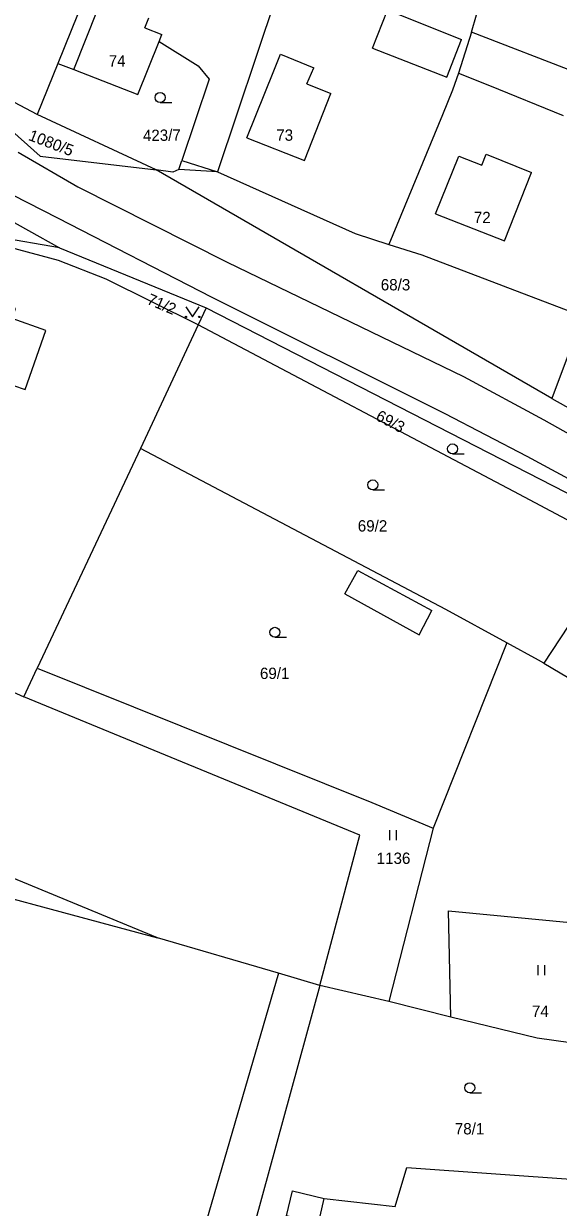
# Model space of a CAD drawing. Extents: x -746176 to -739709, y -1127410 to -1124482.
# Drawn here: x -742472.1 to -742391.9, y -1126088.1 to -1125910.5 of the extents above; entities that cross this region are included whole.
import ezdxf

# ---------------------------------------------------------------- set-up
doc = ezdxf.new("R2010")
doc.units = 0
for name, color, linetype in [('Hranice parcel', 7, 'Continuous'), ('Parcelní čísla', 7, 'Continuous'), ('Vnitřní kresba', 7, 'Continuous'), ('Značky kultur', 7, 'Continuous')]:
    doc.layers.add(name, color=color, linetype=linetype)

msp = doc.modelspace()

# ---------------------------------------------------------------- linework, layer by layer
at = {"layer": 'Hranice parcel'}
for p, q in [((-742459.32, -1125897.41), (-742466.99, -1125916.45)), ((-742404.91, -1125911.78), (-742401.44, -1125899.49)), ((-742433.58, -1125904.47), (-742443.02, -1125932.7)), ((-742470.08, -1125924.13), (-742486.25, -1125915.58)), ((-742466.99, -1125916.45), (-742470.08, -1125924.13)), ((-742452.23, -1125932.44), (-742470.08, -1125924.13)), ((-742392.86, -1125966.72), (-742452.23, -1125932.44)), ((-742485.76, -1125933.54), (-742466.73, -1125944.13)), ((-742466.73, -1125944.13), (-742444.75, -1125953.11)), ((-742444.75, -1125953.11), (-742445.94, -1125955.65)), ((-742445.94, -1125955.65), (-742454.6, -1125974.2)), ((-742454.6, -1125974.2), (-742470.09, -1126007.17)), ((-742399.65, -1126003.37), (-742410.68, -1126031.18)), ((-742472.11, -1126011.47), (-742470.09, -1126007.17)), ((-742452.02, -1126047.65), (-742529.61, -1126015.62)), ((-742410.68, -1126031.18), (-742417.35, -1126057.17)), ((-742433.87, -1126052.94), (-742452.02, -1126047.65)), ((-742427.68, -1126054.77), (-742433.87, -1126052.94)), ((-742417.35, -1126057.17), (-742427.68, -1126054.77)), ((-742408.01, -1126059.51), (-742417.35, -1126057.17))]:
    msp.add_line(p, q, dxfattribs=at)
for points in [[(-742466.99, -1125916.45), (-742464.6, -1125917.38), (-742455, -1125921.11), (-742451.78, -1125913.15), (-742445.93, -1125916.84), (-742444.31, -1125918.83), (-742448.37, -1125931), (-742443.02, -1125932.7)], [(-742404.91, -1125911.78), (-742406.86, -1125917.94), (-742407.78, -1125920.45), (-742409.26, -1125924.16), (-742417.31, -1125943.6)], [(-742376.04, -1125923.32), (-742388.87, -1125917.99), (-742404.91, -1125911.78)], [(-742486.25, -1125915.58), (-742469.64, -1125930.37), (-742452.23, -1125932.44)], [(-742443.02, -1125932.7), (-742448.82, -1125932.36), (-742449.74, -1125932.78), (-742452.23, -1125932.44)], [(-742443.02, -1125932.7), (-742422.4, -1125941.96), (-742417.31, -1125943.6)], [(-742466.73, -1125944.13), (-742476.04, -1125942.52), (-742485.91, -1125941.93), (-742509.68, -1125946.54)], [(-742445.94, -1125955.65), (-742459.75, -1125948.8), (-742466.89, -1125946.02), (-742474.13, -1125944.08), (-742476.37, -1125943.84), (-742485.83, -1125943.85), (-742509.68, -1125946.54)], [(-742417.31, -1125943.6), (-742412.38, -1125945.19), (-742387.99, -1125954.45)], [(-742480.68, -1125962.42), (-742481.12, -1125963.73), (-742480.27, -1125964.02), (-742480.78, -1125965.52), (-742479, -1125966.12), (-742478.49, -1125964.62), (-742477.64, -1125964.9), (-742477.2, -1125963.59), (-742471.89, -1125965.38), (-742468.82, -1125956.52), (-742473.86, -1125954.74), (-742473.34, -1125953.24), (-742475.63, -1125952.43), (-742475.36, -1125951.69), (-742476.67, -1125951.22), (-742476.32, -1125950.24), (-742478.09, -1125949.62), (-742478.44, -1125950.6), (-742479.71, -1125950.15), (-742479.97, -1125950.9), (-742482.31, -1125950.08), (-742485.99, -1125960.63), (-742480.68, -1125962.42)], [(-742444.75, -1125953.11), (-742386.93, -1125982.77), (-742380.97, -1125986.53)], [(-742382.69, -1125989.14), (-742398.6, -1125980.67), (-742445.94, -1125955.65)], [(-742387.99, -1125954.45), (-742389.36, -1125957.36), (-742392.86, -1125966.72)], [(-742392.86, -1125966.72), (-742375.94, -1125976.23), (-742374.7, -1125977.14), (-742365.43, -1125982.55)], [(-742399.65, -1126003.37), (-742408.8, -1125998.36), (-742454.6, -1125974.2)], [(-742525.42, -1125987.39), (-742524.92, -1125987.63), (-742472.11, -1126011.47)], [(-742382.69, -1125989.14), (-742385.4, -1125993.25), (-742394.08, -1126006.45)], [(-742394.08, -1126006.45), (-742394.87, -1126005.98), (-742399.65, -1126003.37)], [(-742470.09, -1126007.17), (-742419.86, -1126027.33), (-742410.68, -1126031.18)], [(-742394.08, -1126006.45), (-742377.42, -1126016.26), (-742373.55, -1126018.6), (-742347.83, -1126023.87), (-742347.76, -1126023.57)], [(-742427.68, -1126054.77), (-742421.67, -1126032.23), (-742472.11, -1126011.47)], [(-742530.79, -1126023.12), (-742529.6, -1126023.26), (-742518.21, -1126026.98), (-742517.74, -1126027.24), (-742518.78, -1126030.97), (-742491.05, -1126037.15), (-742452.02, -1126047.65)], [(-742408.01, -1126059.51), (-742408.36, -1126043.59), (-742380.73, -1126046.24)], [(-742433.87, -1126052.94), (-742447.8, -1126100.68), (-742456.41, -1126109.29), (-742463.16, -1126192.21), (-742472.54, -1126297.27), (-742476.24, -1126360.79), (-742482.39, -1126414.71)], [(-742427.68, -1126054.77), (-742440.74, -1126102.42), (-742430.76, -1126104.41), (-742424.03, -1126105.75), (-742421.29, -1126105.88)], [(-742374.74, -1126065.53), (-742395.07, -1126062.68), (-742408.01, -1126059.51)], [(-742421.29, -1126105.88), (-742421.35, -1126098.94), (-742420.61, -1126091.6), (-742427.91, -1126090.46), (-742432.7, -1126089.32), (-742431.8, -1126085.57), (-742427.02, -1126086.71), (-742416.37, -1126087.94), (-742414.61, -1126082.07), (-742388.6, -1126083.94), (-742388.43, -1126090.91), (-742379.6, -1126093.36)]]:
    msp.add_lwpolyline(points, dxfattribs=at)
at = {"layer": 'Vnitřní kresba'}
for p, q in [((-742464.6, -1125917.38), (-742461.01, -1125908.34)), ((-742453.97, -1125911.14), (-742453.33, -1125909.63)), ((-742419.77, -1125914.17), (-742417.54, -1125908.45)), ((-742416.34, -1125908.93), (-742406.43, -1125912.88)), ((-742453.97, -1125911.14), (-742451.37, -1125912.13)), ((-742451.78, -1125913.15), (-742451.37, -1125912.13)), ((-742408.63, -1125918.53), (-742406.43, -1125912.88)), ((-742419.77, -1125914.17), (-742408.63, -1125918.53)), ((-742434.59, -1125917.55), (-742433.61, -1125915.09)), ((-742433.61, -1125915.09), (-742428.57, -1125917.11)), ((-742438.62, -1125927.64), (-742434.59, -1125917.55)), ((-742429.64, -1125919.52), (-742428.57, -1125917.11)), ((-742406.86, -1125917.94), (-742402.22, -1125919.77)), ((-742429.64, -1125919.52), (-742426.02, -1125920.95)), ((-742402.22, -1125919.77), (-742391.15, -1125924.26)), ((-742430.01, -1125931), (-742426.02, -1125920.95)), ((-742438.62, -1125927.64), (-742430.01, -1125931)), ((-742472.93, -1125929.77), (-742464.02, -1125934.96)), ((-742448.82, -1125932.36), (-742448.37, -1125931)), ((-742410.34, -1125939), (-742406.83, -1125930.35)), ((-742406.83, -1125930.35), (-742403.4, -1125931.74)), ((-742403.4, -1125931.74), (-742402.73, -1125930.07)), ((-742402.73, -1125930.07), (-742395.9, -1125932.8)), ((-742399.99, -1125943.09), (-742395.9, -1125932.8)), ((-742476.09, -1125935.01), (-742467.07, -1125939.61)), ((-742464.02, -1125934.96), (-742441.6, -1125946.26)), ((-742467.07, -1125939.61), (-742443.89, -1125951.53)), ((-742410.34, -1125939), (-742399.99, -1125943.09)), ((-742441.6, -1125946.26), (-742406.15, -1125963.41)), ((-742443.89, -1125951.53), (-742408.92, -1125968.97)), ((-742406.15, -1125963.41), (-742394.08, -1125969.92)), ((-742408.92, -1125968.97), (-742396.61, -1125975.35)), ((-742394.08, -1125969.92), (-742378.39, -1125978.73)), ((-742396.61, -1125975.35), (-742381.3, -1125983.74)), ((-742423.91, -1125996.04), (-742421.99, -1125992.51)), ((-742421.99, -1125992.51), (-742410.9, -1125998.54)), ((-742423.91, -1125996.04), (-742412.8, -1126002.17)), ((-742412.8, -1126002.17), (-742410.9, -1125998.54)), ((-742427.91, -1126090.46), (-742427.02, -1126086.71))]:
    msp.add_line(p, q, dxfattribs=at)
at = {"layer": 'Značky kultur'}
for p, q in [((-742451.653, -1125922.32), (-742449.903, -1125922.32)), ((-742407.773, -1125975.03), (-742406.023, -1125975.03)), ((-742419.743, -1125980.43), (-742417.993, -1125980.43)), ((-742434.423, -1126002.55), (-742432.673, -1126002.55)), ((-742417.161, -1126032.99), (-742417.161, -1126031.49)), ((-742416.16, -1126032.99), (-742416.16, -1126031.49)), ((-742394.931, -1126053.24), (-742394.931, -1126051.74)), ((-742393.93, -1126053.24), (-742393.93, -1126051.74)), ((-742405.183, -1126070.87), (-742403.433, -1126070.87))]:
    msp.add_line(p, q, dxfattribs=at)
msp.add_lwpolyline([(-742447.78, -1125952.989), (-742446.78, -1125954.49), (-742445.78, -1125952.989)], dxfattribs=at)
for centre, radius in [((-742451.653, -1125921.57), 0.75), ((-742447.78, -1125954.489), 0.1), ((-742445.78, -1125954.489), 0.1), ((-742407.773, -1125974.28), 0.75), ((-742419.743, -1125979.68), 0.75), ((-742434.423, -1126001.8), 0.75), ((-742405.183, -1126070.12), 0.75)]:
    msp.add_circle(centre, radius, dxfattribs=at)

# ---------------------------------------------------------------- texts
at = {"layer": 'Parcelní čísla'}
for s, p in [('74', (-742459.362, -1125916.92)), ('73', (-742434.222, -1125928.06)), ('72', (-742404.582, -1125940.42)), ('68/3', (-742418.541, -1125950.51)), ('69/2', (-742421.991, -1125986.68)), ('69/1', (-742436.671, -1126008.8)), ('1136', (-742419.157, -1126036.54)), ('74', (-742395.862, -1126059.49)), ('78/1', (-742407.431, -1126077.12))]:
    msp.add_text(s, height=1.7, dxfattribs=at).set_placement(p)
for s, rotation, p in [('1080/5', 339, (-742471.534, -1125927.913)), ('423/7', 1, (-742454.218, -1125928.128)), ('71/2', 337, (-742453.774, -1125952.486)), ('69/3', 332, (-742419.427, -1125969.868))]:
    msp.add_text(s, height=1.7, rotation=rotation, dxfattribs=at).set_placement(p)

doc.saveas('drawing.dxf')
